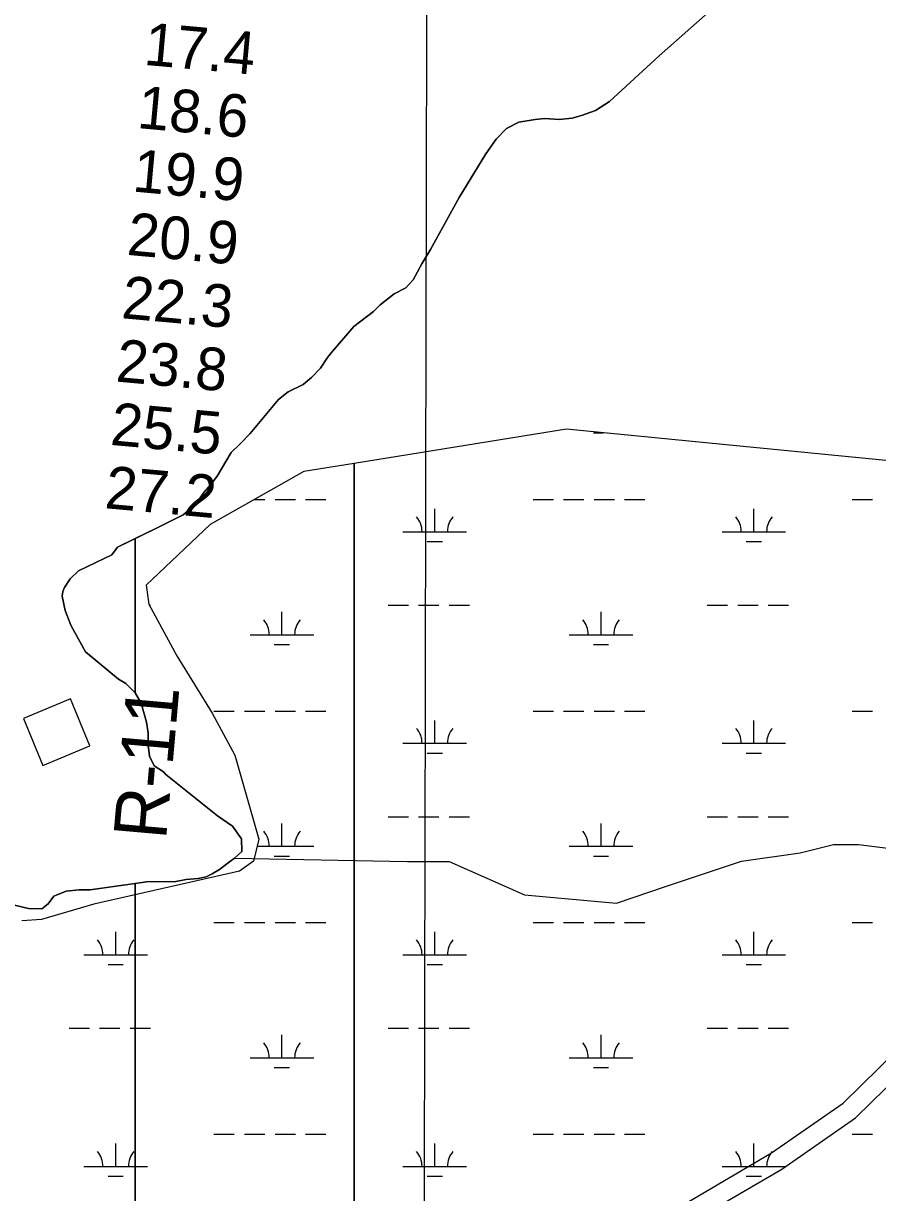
# Model space of a CAD drawing. Extents: x 3192927 to 3230760, y 831141 to 856475.
# Drawn here: x 3206954 to 3208298, y 845022 to 846860 of the extents above; entities that cross this region are included whole.
import ezdxf

# ---------------------------------------------------------------- set-up
doc = ezdxf.new("R2010")
doc.units = 0
for name, color, linetype in [('V-BLDG-OTLN', 7, 'Continuous'), ('V-GRID-MAJR', 7, 'Continuous'), ('V-RIVR-RANG', 7, 'Continuous'), ('V-RIVR-RANG-IDEN', 7, 'Continuous'), ('V-ROAD-CNTR', 7, 'Continuous'), ('V-SITE-VEGE', 7, 'Continuous'), ('V-TOPO-SHOR', 7, 'Continuous'), ('V-WETL-SWMP', 7, 'Continuous')]:
    doc.layers.add(name, color=color, linetype=linetype)

msp = doc.modelspace()

# ---------------------------------------------------------------- linework, layer by layer
at = {"layer": 'V-BLDG-OTLN'}
msp.add_lwpolyline([(3207028.4, 845798.1), (3206954.6, 845767.3), (3206985.3, 845693.4), (3207059.2, 845724.2)], close=True, dxfattribs=at)
at = {"layer": 'V-GRID-MAJR'}
msp.add_spline([(3207568.4, 836526.3), (3207580.8, 842585.6), (3207593.1, 848648), (3207605.4, 854710.5), (3207605.4, 854713.5)], degree=3, dxfattribs=at)
at = {"layer": 'V-ROAD-CNTR'}
for points in [[(3207535.3, 844655.9), (3207631.2, 844734.8), (3207724.3, 844807), (3207771.9, 844848.5), (3207872.5, 844921.1), (3207998.3, 845006), (3208131.2, 845083.9), (3208243.9, 845162.3), (3208357.7, 845273.6), (3208424, 845373.9), (3208427.4, 845401.4)], [(3207558.2, 844635.9), (3207650, 844711.4), (3207743.4, 844783.8), (3207790.5, 844825), (3207889.7, 844896.4), (3208014.3, 844980.6), (3208147.4, 845058.6), (3208263.1, 845139.1), (3208380.9, 845254.4), (3208453, 845363.3), (3208457.8, 845403.2)]]:
    msp.add_lwpolyline(points, dxfattribs=at)
at = {"layer": 'V-SITE-VEGE'}
for points in [[(3208054, 846897.6), (3207954.5, 846809.1), (3207876.3, 846737.2), (3207854.2, 846723), (3207832.2, 846715.1), (3207817.6, 846711), (3207797, 846709.1), (3207774.8, 846710.3), (3207759.1, 846709.2), (3207733.8, 846704.6), (3207714.5, 846694.8), (3207698, 846677.8), (3207682, 846655), (3207639.8, 846586.1), (3207594.7, 846504.3), (3207581.2, 846481.8)], [(3207581.2, 846481.8), (3207567.4, 846457.1), (3207556.1, 846444.5), (3207537.4, 846434.9), (3207515.4, 846417.6), (3207505.2, 846406.9), (3207474, 846383.6), (3207439, 846342.8), (3207433, 846334.9), (3207421.9, 846318.2), (3207407.4, 846303.3), (3207394.6, 846292.4), (3207371, 846281), (3207355.7, 846268.6), (3207311.3, 846215.4), (3207295.6, 846199), (3207281, 846185.2), (3207259.2, 846148), (3207249.3, 846135.2), (3207238.3, 846122.4), (3207225, 846103.8), (3207205.5, 846087.5), (3207162.6, 846065.7), (3207130.3, 846049.9), (3207130.3, 845807.2), (3207139.7, 845791.3), (3207148, 845761.2), (3207150.6, 845744.8), (3207150.6, 845725.2), (3207152.8, 845707.9), (3207160, 845692.6), (3207175, 845683.1), (3207178.6, 845679.2), (3207260, 845614.1), (3207283.4, 845597.6), (3207297.3, 845577.7), (3207297.9, 845558.1), (3207286.5, 845547.4), (3207274.3, 845538.8), (3207263.1, 845529.6), (3207251.5, 845523), (3207242, 845518), (3207229.3, 845515.6), (3207210.6, 845513.8), (3207191.5, 845510.1), (3207151.5, 845510.7), (3207130.3, 845507.8), (3207130.3, 841090.9)], [(3207130.3, 844014.4), (3207130.3, 845507.8), (3207059.4, 845497.9), (3207042.2, 845497.6), (3207021.6, 845495.6), (3207002.5, 845487.5), (3206993.2, 845475.6), (3206983.3, 845467.6), (3206962.7, 845468.3), (3206803.6, 845505.8)]]:
    msp.add_lwpolyline(points, dxfattribs=at)
msp.add_lwpolyline([(3207130.3, 846049.9), (3207102.5, 846036.3), (3207093.8, 846024.4), (3207041, 845999.1), (3207028.2, 845986.5), (3207019.1, 845973.3), (3207016.4, 845966.8), (3207015.4, 845959.3), (3207020.2, 845936.9), (3207029.3, 845914.1), (3207035.2, 845902.2), (3207052.1, 845871.8), (3207104.2, 845829.1), (3207115.5, 845822.1), (3207130.2, 845807.4), (3207130.3, 845807.2)], close=True, dxfattribs=at)
at = {"layer": 'V-TOPO-SHOR'}
for points in [[(3207439, 846342.8), (3207474, 846383.6), (3207505.2, 846406.9), (3207515.4, 846417.6), (3207537.4, 846434.9), (3207556.1, 846444.5), (3207567.4, 846457.1), (3207581.2, 846481.8), (3207594.7, 846504.3), (3207639.8, 846586.1), (3207682, 846655), (3207698, 846677.8), (3207714.5, 846694.8), (3207733.8, 846704.6), (3207759.1, 846709.2), (3207774.8, 846710.3), (3207797, 846709.1), (3207817.6, 846711), (3207832.2, 846715.1), (3207854.2, 846723), (3207876.3, 846737.2), (3207954.5, 846809.1), (3208054, 846897.6)], [(3206803.6, 845505.8), (3206962.7, 845468.3), (3206983.3, 845467.6), (3206993.2, 845475.6), (3207002.5, 845487.5), (3207021.6, 845495.6), (3207042.2, 845497.6), (3207059.4, 845497.9), (3207151.5, 845510.7), (3207191.5, 845510.1), (3207210.6, 845513.8), (3207229.3, 845515.6), (3207242, 845518), (3207251.5, 845522.9), (3207263.1, 845529.6), (3207274.3, 845538.8), (3207286.5, 845547.4), (3207297.9, 845558.1), (3207297.3, 845577.7), (3207283.4, 845597.6), (3207260, 845614.1), (3207178.6, 845679.2), (3207175, 845683.1), (3207160, 845692.6), (3207152.8, 845707.9), (3207150.6, 845725.2), (3207150.6, 845744.8), (3207148, 845761.2), (3207139.7, 845791.3), (3207130.2, 845807.4), (3207115.5, 845822.1), (3207104.2, 845829.1), (3207052.1, 845871.8), (3207035.2, 845902.2), (3207029.3, 845914.1), (3207020.2, 845936.9), (3207015.4, 845959.3), (3207016.4, 845966.8), (3207019.1, 845973.3), (3207028.2, 845986.5), (3207041, 845999.1), (3207093.8, 846024.4), (3207102.5, 846036.3), (3207162.6, 846065.7), (3207205.5, 846087.5), (3207225, 846103.8), (3207238.3, 846122.4), (3207249.3, 846135.2), (3207259.2, 846148), (3207281, 846185.2), (3207295.6, 846199), (3207311.3, 846215.4), (3207355.7, 846268.6), (3207371, 846281), (3207394.6, 846292.4), (3207407.4, 846303.3), (3207421.9, 846318.2), (3207433, 846334.9), (3207439, 846342.8)], [(3207286.5, 845547.4), (3207558.3, 845542.3), (3207624.1, 845542.3), (3207742.4, 845489.8), (3207887, 845476.8), (3207965.8, 845503.2), (3208084.1, 845542.7), (3208176.1, 845555.9), (3208228.6, 845569.1), (3208268.1, 845569.1), (3208373.2, 845556.1), (3208557.3, 845516.8), (3208662.5, 845438), (3208741.4, 845385.5), (3208846.6, 845333), (3208991.2, 845293.7), (3209148.9, 845267.5), (3209267.3, 845215.1), (3209359.3, 845188.9), (3209425, 845188.9), (3209530.1, 845221.9)]]:
    msp.add_lwpolyline(points, dxfattribs=at)
at = {"layer": 'V-WETL-SWMP'}
for p, q in [((3207850.9, 846216.2), (3207866.1, 846216.2)), ((3207317.6, 846111.5), (3207334.2, 846111.5)), ((3207350.2, 846111.5), (3207382.2, 846111.5)), ((3207398.2, 846111.5), (3207430.2, 846111.5)), ((3207756, 846111.5), (3207788, 846111.5)), ((3207804, 846111.5), (3207836, 846111.5)), ((3207852, 846111.5), (3207884, 846111.5)), ((3207900, 846111.5), (3207932, 846111.5)), ((3208257.9, 846111.5), (3208289.9, 846111.5)), ((3207601.4, 846060.8), (3207601.4, 846096.8)), ((3208103.3, 846060.8), (3208103.3, 846096.8)), ((3207551.4, 846060.8), (3207651.4, 846060.8)), ((3208053.3, 846060.8), (3208153.3, 846060.8)), ((3207589.4, 846045.3), (3207613.4, 846045.3)), ((3208091.3, 846045.3), (3208115.3, 846045.3)), ((3207152.7, 845945.3), (3207154.2, 845945.3)), ((3207528, 845945.3), (3207560, 845945.3)), ((3207576, 845945.3), (3207608, 845945.3)), ((3207624, 845945.3), (3207656, 845945.3)), ((3208029.9, 845945.3), (3208061.9, 845945.3)), ((3208077.9, 845945.3), (3208109.9, 845945.3)), ((3208125.9, 845945.3), (3208157.9, 845945.3)), ((3207361, 845898.9), (3207361, 845934.9)), ((3207862.9, 845898.9), (3207862.9, 845934.9)), ((3207311, 845898.9), (3207411, 845898.9)), ((3207812.9, 845898.9), (3207912.9, 845898.9)), ((3207349, 845883.5), (3207373, 845883.5)), ((3207850.9, 845883.5), (3207874.9, 845883.5)), ((3207254.2, 845778.8), (3207286.2, 845778.8)), ((3207302.2, 845778.8), (3207334.2, 845778.8)), ((3207350.2, 845778.8), (3207382.2, 845778.8)), ((3207398.2, 845778.8), (3207430.2, 845778.8)), ((3207756, 845778.8), (3207788, 845778.8)), ((3207804, 845778.8), (3207836, 845778.8)), ((3207852, 845778.8), (3207884, 845778.8)), ((3207900, 845778.8), (3207932, 845778.8)), ((3208257.9, 845778.8), (3208289.9, 845778.8)), ((3207601.4, 845728.1), (3207601.4, 845764.1)), ((3208103.3, 845728.1), (3208103.3, 845764.1)), ((3207551.4, 845728.1), (3207651.4, 845728.1)), ((3208053.3, 845728.1), (3208153.3, 845728.1)), ((3207589.4, 845712.7), (3207613.4, 845712.7)), ((3208091.3, 845712.7), (3208115.3, 845712.7)), ((3207528, 845612.7), (3207560, 845612.7)), ((3207576, 845612.7), (3207608, 845612.7)), ((3207624, 845612.7), (3207656, 845612.7)), ((3208029.9, 845612.7), (3208061.9, 845612.7)), ((3208077.9, 845612.7), (3208109.9, 845612.7)), ((3208125.9, 845612.7), (3208157.9, 845612.7)), ((3207361, 845566.2), (3207361, 845602.2)), ((3207862.9, 845566.2), (3207862.9, 845602.2)), ((3207322.2, 845566.2), (3207411, 845566.2)), ((3207812.9, 845566.2), (3207912.9, 845566.2)), ((3207349, 845550.8), (3207373, 845550.8)), ((3207850.9, 845550.8), (3207874.9, 845550.8)), ((3207254.2, 845446.2), (3207286.2, 845446.2)), ((3207302.2, 845446.2), (3207334.2, 845446.2)), ((3207350.2, 845446.2), (3207382.2, 845446.2)), ((3207398.2, 845446.2), (3207430.2, 845446.2)), ((3207756, 845446.2), (3207788, 845446.2)), ((3207804, 845446.2), (3207836, 845446.2)), ((3207852, 845446.2), (3207884, 845446.2)), ((3207900, 845446.2), (3207932, 845446.2)), ((3208257.9, 845446.2), (3208289.9, 845446.2)), ((3207099.6, 845395.4), (3207099.6, 845431.4)), ((3207601.4, 845395.4), (3207601.4, 845431.4)), ((3208103.3, 845395.4), (3208103.3, 845431.4)), ((3207049.6, 845395.4), (3207149.6, 845395.4)), ((3207551.4, 845395.4), (3207651.4, 845395.4)), ((3208053.3, 845395.4), (3208153.3, 845395.4)), ((3207087.6, 845380), (3207111.6, 845380)), ((3207589.4, 845380), (3207613.4, 845380)), ((3208091.3, 845380), (3208115.3, 845380)), ((3207026.2, 845280), (3207058.2, 845280)), ((3207074.2, 845280), (3207106.2, 845280)), ((3207122.2, 845280), (3207154.2, 845280)), ((3207528, 845280), (3207560, 845280)), ((3207576, 845280), (3207608, 845280)), ((3207624, 845280), (3207656, 845280)), ((3208029.9, 845280), (3208061.9, 845280)), ((3208077.9, 845280), (3208109.9, 845280)), ((3208125.9, 845280), (3208157.9, 845280)), ((3207361, 845233.6), (3207361, 845269.6)), ((3207862.9, 845233.6), (3207862.9, 845269.6)), ((3207311, 845233.6), (3207411, 845233.6)), ((3207812.9, 845233.6), (3207912.9, 845233.6)), ((3207349, 845218.1), (3207373, 845218.1)), ((3207850.9, 845218.1), (3207874.9, 845218.1)), ((3207099.6, 845062.8), (3207099.6, 845098.8)), ((3207254.2, 845113.5), (3207286.2, 845113.5)), ((3207302.2, 845113.5), (3207334.2, 845113.5)), ((3207350.2, 845113.5), (3207382.2, 845113.5)), ((3207398.2, 845113.5), (3207430.2, 845113.5)), ((3207601.4, 845062.8), (3207601.4, 845098.8)), ((3207756, 845113.5), (3207788, 845113.5)), ((3207804, 845113.5), (3207836, 845113.5)), ((3207852, 845113.5), (3207884, 845113.5)), ((3207900, 845113.5), (3207932, 845113.5)), ((3208103.3, 845062.8), (3208103.3, 845098.8)), ((3208257.9, 845113.5), (3208289.9, 845113.5)), ((3207049.6, 845062.8), (3207149.6, 845062.8)), ((3207551.4, 845062.8), (3207651.4, 845062.8)), ((3208053.3, 845062.8), (3208153.3, 845062.8)), ((3207087.6, 845047.3), (3207111.6, 845047.3)), ((3207589.4, 845047.3), (3207613.4, 845047.3)), ((3208091.3, 845047.3), (3208115.3, 845047.3))]:
    msp.add_line(p, q, dxfattribs=at)
for points in [[(3209221.5, 846177.3), (3209209.7, 846164.8), (3209176.7, 846146), (3209124.9, 846137.5), (3209089.7, 846139.2), (3209060.7, 846140.1), (3208928.2, 846123.2), (3208872.5, 846117.8), (3207808.6, 846221.8), (3207474.8, 846168.1), (3207474.8, 840421.2)], [(3205504, 839678), (3207474.8, 839678), (3207474.8, 846168.1), (3207395.3, 846155.3), (3207248, 846072.2), (3207147.4, 845976.9), (3207151.9, 845946.7), (3207195.8, 845865.5), (3207251.5, 845775.5), (3207286.8, 845709.4), (3207324.8, 845577.4), (3207316.6, 845542.6), (3207294.3, 845526.9), (3207065.5, 845475.2), (3206982.8, 845451.2), (3206951.9, 845449)]]:
    msp.add_lwpolyline(points, dxfattribs=at)
for centre, start, end in [((3207546.2, 846061.3), 359.2282, 40.7718), ((3207656.7, 846061.3), 139.2282, 180.7718), ((3208048.1, 846061.3), 359.2282, 40.7718), ((3208158.6, 846061.3), 139.2282, 180.7718), ((3207305.8, 845899.4), 359.2282, 40.7718), ((3207416.3, 845899.4), 139.2282, 180.7718), ((3207807.6, 845899.4), 359.2282, 40.7718), ((3207918.1, 845899.4), 139.2282, 180.7718), ((3207546.2, 845728.6), 359.2282, 40.7718), ((3207656.7, 845728.6), 139.2282, 180.7718), ((3208048.1, 845728.6), 359.2282, 40.7718), ((3208158.6, 845728.6), 139.2282, 180.7718), ((3207305.8, 845566.7), 359.2282, 40.7718), ((3207416.3, 845566.7), 139.2282, 180.7718), ((3207807.6, 845566.7), 359.2282, 40.7718), ((3207918.1, 845566.7), 139.2282, 180.7718), ((3207044.4, 845395.9), 359.2282, 40.7718), ((3207154.8, 845395.9), 139.2282, 180.7718), ((3207546.2, 845395.9), 359.2282, 40.7718), ((3207656.7, 845395.9), 139.2282, 180.7718), ((3208048.1, 845395.9), 359.2282, 40.7718), ((3208158.6, 845395.9), 139.2282, 180.7718), ((3207305.8, 845234), 359.2282, 40.7718), ((3207416.3, 845234), 139.2282, 180.7718), ((3207807.6, 845234), 359.2282, 40.7718), ((3207918.1, 845234), 139.2282, 180.7718), ((3207044.4, 845063.2), 359.2282, 40.7718), ((3207154.8, 845063.2), 139.2282, 180.7718), ((3207546.2, 845063.2), 359.2282, 40.7718), ((3207656.7, 845063.2), 139.2282, 180.7718), ((3208048.1, 845063.2), 359.2282, 40.7718), ((3208158.6, 845063.2), 139.2282, 180.7718)]:
    msp.add_arc(centre, 35.2, start, end, dxfattribs=at)

# ---------------------------------------------------------------- texts
at = {"layer": 'V-RIVR-RANG'}
for s, p in [('17.4', (3207142.6, 846795.1)), ('18.6', (3207132, 846695.7)), ('19.9', (3207124.7, 846595.9)), ('20.9', (3207116, 846496.3)), ('22.3', (3207107.4, 846396.7)), ('23.8', (3207098.6, 846297.1)), ('25.5', (3207089.9, 846197.5)), ('27.2', (3207081.1, 846097.9))]:
    msp.add_text(s, height=67, rotation=354.8183, dxfattribs=at).set_placement(p)
at = {"layer": 'V-RIVR-RANG-IDEN'}
msp.add_text('R-11', height=83, rotation=84.9578, dxfattribs=at).set_placement((3207178.7, 845575.2))

doc.saveas('drawing.dxf')
